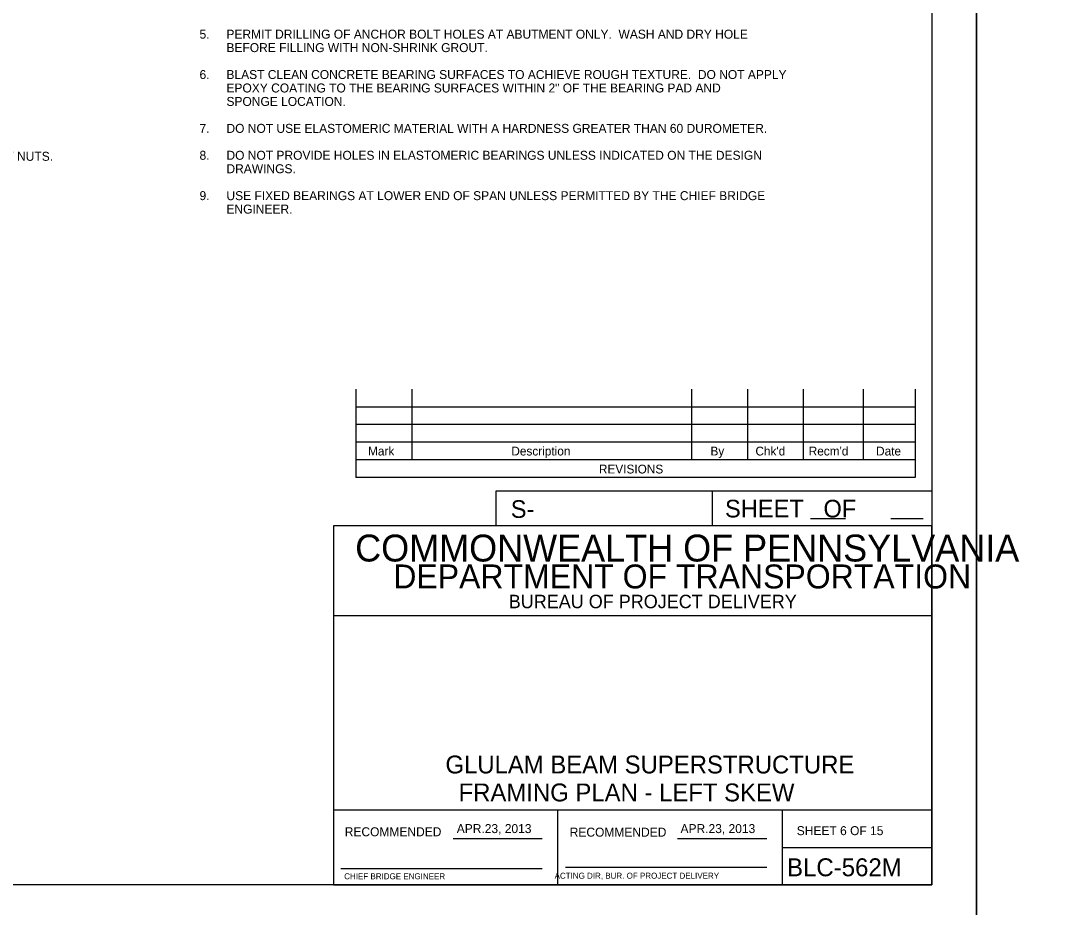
# Model space of a CAD drawing. Extents: x 638263 to 640391, y 293683 to 298655.
# Drawn here: x 638956.9 to 639303.1, y 294879 to 295175.4 of the extents above; entities that cross this region are included whole.
import ezdxf

# ---------------------------------------------------------------- set-up
doc = ezdxf.new("R2010")
doc.units = 0
for name, color, linetype in [('2', 7, 'Continuous'), ('4', 7, 'Continuous'), ('PLT-BNDY', 7, 'Continuous')]:
    doc.layers.add(name, color=color, linetype=linetype)

msp = doc.modelspace()

# ---------------------------------------------------------------- linework, layer by layer
at = {"layer": '2'}
for p, q in [((639261.46, 295450.46), (639261.46, 294886.46)), ((639068.92, 295052.15), (639068.92, 295022.62)), ((639087.62, 295052.15), (639087.62, 295028.53)), ((639181.13, 295052.15), (639181.13, 295028.53)), ((639199.83, 295052.15), (639199.83, 295028.53)), ((639218.53, 295052.15), (639218.53, 295028.53)), ((639238.59, 295052.15), (639238.59, 295028.53)), ((639255.94, 295052.15), (639255.94, 295022.62)), ((639255.94, 295046.24), (639068.92, 295046.24)), ((639255.94, 295040.34), (639068.92, 295040.34)), ((639255.94, 295034.43), (639068.92, 295034.43)), ((639255.94, 295028.53), (639068.92, 295028.53)), ((639255.94, 295022.62), (639068.92, 295022.62)), ((639261.46, 295018.11), (639115.78, 295018.11)), ((639115.78, 295018.11), (639115.78, 295006.46)), ((639188.09, 295018.11), (639188.09, 295006.46)), ((639261.46, 295006.46), (639061.46, 295006.46)), ((639061.46, 295006.46), (639061.46, 294886.46)), ((639220.95, 295009), (639232.6, 295009)), ((639247.83, 295009), (639258.56, 295009)), ((639261.46, 294886.46), (639261.46, 295006.46)), ((639261.46, 294976.46), (639061.46, 294976.46)), ((639261.46, 294911.46), (639061.46, 294911.46)), ((639136.46, 294886.46), (639136.46, 294911.46)), ((639211.46, 294911.46), (639211.46, 294886.46)), ((639101.42, 294901.96), (639131.19, 294901.96)), ((639176.42, 294901.96), (639206.33, 294901.96)), ((639211.46, 294898.96), (639261.46, 294898.96)), ((639139.08, 294892.33), (639206.33, 294892.33)), ((639063.96, 294891.96), (639131.19, 294891.96)), ((639261.46, 294886.46), (638475.46, 294886.46)), ((639061.46, 294886.46), (639261.46, 294886.46))]:
    msp.add_line(p, q, dxfattribs=at)
at = {"layer": 'PLT-BNDY'}
for points in [[(638435.46, 295465.46), (639276.46, 295465.46), (639276.46, 294871.46), (638435.46, 294871.46)], [(639276.46, 295465.46), (640117.46, 295465.46), (640117.46, 294871.46), (639276.46, 294871.46)]]:
    msp.add_lwpolyline(points, close=True, dxfattribs=at)

# ---------------------------------------------------------------- texts
at = {"layer": '2'}
for s, height, p in [('Mark', 2.952, (639073.02, 295030.03)), ('Description', 2.9523, (639120.92, 295030.03)), ('By', 2.952, (639187.49, 295030.03)), ("Chk'd", 2.952, (639202.52, 295030.03)), ("Recm'd", 2.953, (639220.33, 295030.03)), ('Date', 2.952, (639242.86, 295030.03)), ('REVISIONS', 2.952, (639150.2, 295024.01)), ('S-', 5.905, (639120.73, 295009.17)), ('COMMONWEALTH OF PENNSYLVANIA', 9, (639068.71, 294994.58)), ('DEPARTMENT OF TRANSPORTATION', 8.0002, (639081.46, 294985.58)), ('BUREAU OF PROJECT DELIVERY', 4.5, (639120.05, 294978.96)), ('FRAMING PLAN - LEFT SKEW', 5.9728, (639103.29, 294914.37)), ('APR.23, 2013', 3, (639102.67, 294903.77)), ('APR.23, 2013', 3, (639177.48, 294903.77)), ('SHEET 6 OF 15', 3, (639216.33, 294903.08)), ('BLC-562M', 6, (639213.08, 294889.33)), ('CHIEF BRIDGE ENGINEER', 2.0002, (639065.05, 294888.33)), ('  ACTING DIR, BUR. OF PROJECT DELIVERY', 2.0002, (639133.9, 294888.51))]:
    msp.add_text(s, height=height, dxfattribs=at).set_placement(p)
for s, height, p in [('SHEET   OF', 5.907, (639192.35, 295009.31)), ('RECOMMENDED', 3, (639065.23, 294902.71)), ('RECOMMENDED', 3, (639140.44, 294902.58))]:
    msp.add_text(s, height=height, rotation=360, dxfattribs=at).set_placement(p)
at = {"layer": '4'}
for s, height, p in [('5.', 3, (639016.68, 295169.41)), ('PERMIT DRILLING OF ANCHOR BOLT HOLES AT ABUTMENT ONLY.  WASH AND DRY HOLE', 3, (639025.68, 295169.41)), ('BEFORE FILLING WITH NON-SHRINK GROUT.', 3, (639025.68, 295164.91)), ('6.', 3, (639016.68, 295155.91)), ('BLAST CLEAN CONCRETE BEARING SURFACES TO ACHIEVE ROUGH TEXTURE.  DO NOT APPLY', 3, (639025.68, 295155.91)), ('EPOXY COATING TO THE BEARING SURFACES WITHIN 2" OF THE BEARING PAD AND', 3, (639025.68, 295151.41)), ('SPONGE LOCATION.', 3, (639025.68, 295146.91)), ('7.', 3, (639016.68, 295137.91)), ('DO NOT USE ELASTOMERIC MATERIAL WITH A HARDNESS GREATER THAN 60 DUROMETER.', 3, (639025.68, 295137.91)), ('TURN AND PEEN BOLT THREADS AT FACE OF NUTS.', 3, (638865.19, 295128.57)), ('8.', 3, (639016.68, 295128.91)), ('DO NOT PROVIDE HOLES IN ELASTOMERIC BEARINGS UNLESS INDICATED ON THE DESIGN', 3, (639025.68, 295128.91)), ('DRAWINGS.', 3, (639025.68, 295124.41)), ('9.', 3, (639016.68, 295115.41)), ('USE FIXED BEARINGS AT LOWER END OF SPAN UNLESS PERMITTED BY THE CHIEF BRIDGE ', 3, (639025.68, 295115.41)), ('ENGINEER.', 3, (639025.68, 295110.91)), ('GLULAM BEAM SUPERSTRUCTURE', 5.9728, (639098.89, 294923.71))]:
    msp.add_text(s, height=height, dxfattribs=at).set_placement(p)

doc.saveas('drawing.dxf')
